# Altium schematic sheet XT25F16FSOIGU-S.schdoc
size 127 x 101 mm
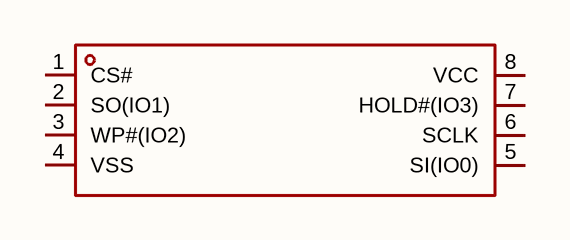
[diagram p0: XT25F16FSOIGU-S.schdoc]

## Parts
U?  xt25f16fsoigu-s  [SOP-8_L4.9-W3.9-P1.27-LS6.0-BL]  (value not drawn)

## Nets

Not connected (* = marked no-connect by the designer): U? 1(CS#) 2(SO(IO1)) 3(WP#(IO2)) 4(VSS) 5(SI(IO0)) 6(SCLK) 7(HOLD#(IO3)) 8(VCC)

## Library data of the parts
U? = xt25f16fsoigu-s: 接口类型:SPI;存储容量:16Mbit;时钟频率(fc):133MHz;; Manufacturer: XTX(芯天下); AddInBom: yes; ModelId: 75c24a7891ee4dd6bdac16a7163ff87e; ModelName: SOP-8_L4.9-W3.9-P1.27-LS6.0-BL-1; ModelTransform: 192.913,236.22,0,0,0,0,-0.393,2.749,0; Interface: SPI; Memory Size: 16Mbit; Clock Frequency: 133MHz; Voltage - Supply: 2.3V~3.6V; Standby Supply Current: 0.3uA; Program / Erase Cycles: 100000次; Page Programming Time (Tpp): 400us; Data Retention - TDR (Year): 20年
